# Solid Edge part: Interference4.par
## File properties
Last saved by: Administrator
Revision: 51
Accuracy: 0.99
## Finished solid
Body 1: solid body, 4 faces, 4 edges, 2 vertices.
  Faces by surface: cone 2, plane 2
  Edges by curve: circle 2, intersection 1, line 1
Bounding box of the edges (mm): 0.037 x 0.085 x 0.148, from (0.5503, -0.0852, 10.9259) to (0.587, 0, 11.0741).
Conical faces (half-angle, radius in mm at the cone's reference point): 27.3968 deg R0.0554 x2
Planar faces by outward normal: +x 1, oblique 1
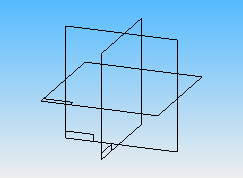
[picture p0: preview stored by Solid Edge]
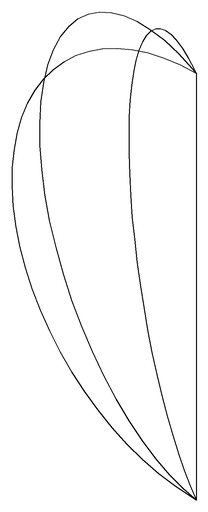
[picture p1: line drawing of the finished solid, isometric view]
